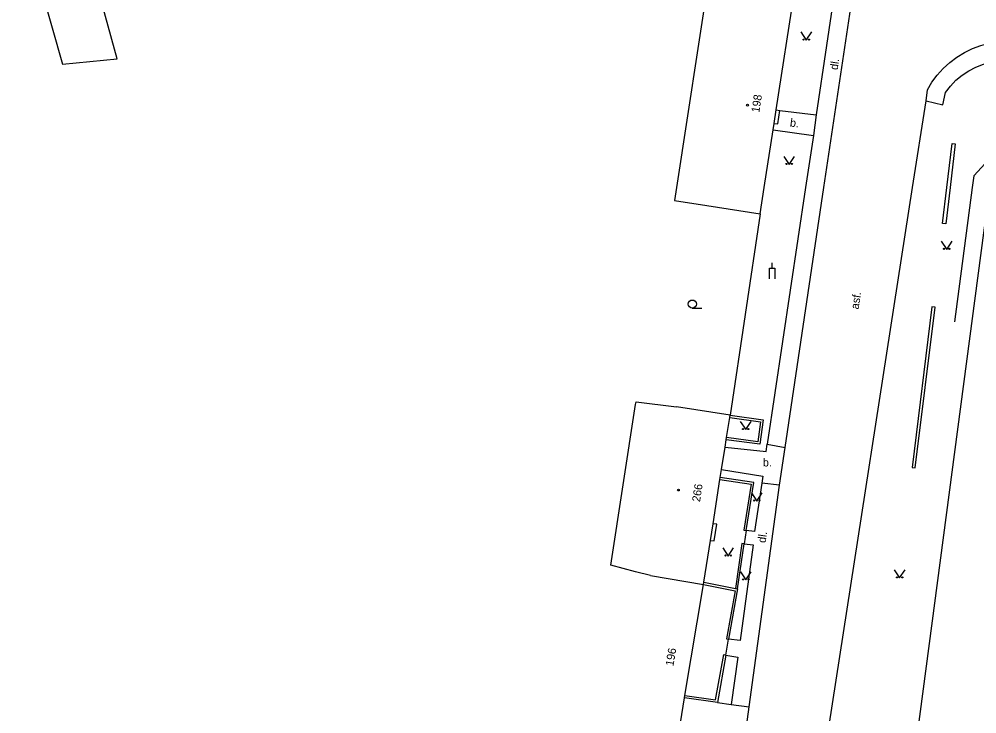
# Model space of a CAD drawing. Extents: x -582162 to -561283, y -1187583 to -1183539.
# Drawn here: x -575057.1 to -574968.4, y -1184048.7 to -1183984.4 of the extents above; entities that cross this region are included whole.
import ezdxf

# ---------------------------------------------------------------- set-up
doc = ezdxf.new("R2010")
doc.units = 0
for name, color, linetype in [('Vrstva 1', 7, 'Continuous'), ('Vrstva 10', 7, 'Continuous'), ('Vrstva 14', 7, 'Continuous'), ('Vrstva 3', 7, 'Continuous'), ('Vrstva 4', 7, 'Continuous'), ('Vrstva 5', 7, 'Continuous'), ('Vrstva 6', 7, 'Continuous'), ('Vrstva 8', 7, 'Continuous'), ('Vrstva 9', 7, 'Continuous')]:
    doc.layers.add(name, color=color, linetype=linetype)

# ---------------------------------------------------------------- blocks, each defined once
blk = doc.blocks.new('3.040')
at = {"layer": 'Vrstva 1'}
blk.add_line((0, -0.75), (1.75, -0.75), dxfattribs=at)
blk.add_circle((0, 0), 0.75, dxfattribs=at)
blk = doc.blocks.new('3.140')
at = {"layer": 'Vrstva 1'}
blk.add_lwpolyline([(-1, 1.5), (0, 0), (1, 1.5)], dxfattribs=at)
for centre in [(-0.5, 0.1), (0.5, 0.1)]:
    blk.add_circle(centre, 0.1, dxfattribs=at)
blk = doc.blocks.new('4.020')
at = {"layer": 'Vrstva 1'}
blk.add_circle((0, 0), 0.175, dxfattribs=at)
blk = doc.blocks.new('4.120')
at = {"layer": 'Vrstva 1'}
blk.add_line((0, 2), (0, 3), dxfattribs=at)
blk.add_lwpolyline([(-0.5, 0), (-0.5, 2), (0.5, 2), (0.5, 0)], dxfattribs=at)

msp = doc.modelspace()

# ---------------------------------------------------------------- linework, layer by layer
at = {"layer": 'Vrstva 10'}
for points in [[(-574982.59, -1184000), (-574979.64, -1183980.23), (-574979.73, -1183979.92), (-574979.89, -1183979.63), (-574980.11, -1183979.4), (-574980.38, -1183979.22), (-574980.69, -1183979.12), (-574980.84, -1183979.1), (-574991.91, -1183976.49)], [(-574992.2, -1183977.87), (-574981.38, -1183980.41), (-574983.3, -1183993.27)], [(-574973.13, -1183991.97), (-574973, -1183990.96), (-574972.58, -1183990.25), (-574972.09, -1183989.59), (-574971.54, -1183988.97), (-574970.93, -1183988.42), (-574970.27, -1183987.92), (-574969.57, -1183987.49), (-574968.83, -1183987.13), (-574968.05, -1183986.84), (-574967.84, -1183986.78), (-574966.96, -1183986.67), (-574966.07, -1183986.64), (-574965.18, -1183986.7), (-574964.81, -1183986.74), (-574962.92, -1183987.44), (-574940.13, -1183995.55), (-574927.84, -1184000)], [(-574973.13, -1183991.97), (-574971.56, -1183992.33), (-574971.34, -1183991.19), (-574970.88, -1183990.61), (-574970.36, -1183990.07), (-574969.79, -1183989.6), (-574969.17, -1183989.19), (-574968.51, -1183988.85), (-574967.81, -1183988.58), (-574967.23, -1183988.42), (-574966.15, -1183988.57), (-574964.51, -1183989.14), (-574964.37, -1183988.73), (-574940.58, -1183997.21), (-574932.83, -1184000)], [(-574974.37, -1184000), (-574973.13, -1183991.97)], [(-574986.66, -1183992.86), (-574983.3, -1183993.27)], [(-574983.3, -1183993.27), (-574983.55, -1183995.19)], [(-574987.28, -1183994.67), (-574983.55, -1183995.19)], [(-574983.55, -1183995.19), (-574984.27, -1184000)], [(-574984.19, -1184112.37), (-574985.15, -1184111.93), (-574985.81, -1184111.44), (-574986.43, -1184110.88), (-574986.99, -1184110.26), (-574987.49, -1184109.59), (-574987.93, -1184108.87), (-574988.29, -1184108.12), (-574988.59, -1184107.33), (-574988.8, -1184106.52), (-574988.94, -1184105.7), (-574989, -1184104.86), (-574982.11, -1184050.01), (-574974.37, -1184000)], [(-574984.27, -1184000), (-574987.82, -1184023.77)], [(-574986.18, -1184024.06), (-574982.59, -1184000)], [(-574965.69, -1184110.12), (-574979.74, -1184104.56), (-574975.79, -1184064.83), (-574967.23, -1184000)], [(-574991.73, -1184024.03), (-574987.92, -1184024.44), (-574987.82, -1184023.77)], [(-574987.82, -1184023.77), (-574986.18, -1184024.06)], [(-574986.68, -1184027.56), (-574986.18, -1184024.06)], [(-574992.05, -1184026.11), (-574988.24, -1184026.74), (-574988.33, -1184027.37)], [(-574988.33, -1184027.37), (-574988.99, -1184031.84), (-574989.78, -1184031.76)], [(-574989.5, -1184048.09), (-574986.68, -1184027.56)], [(-574986.68, -1184027.56), (-574988.33, -1184027.37)], [(-574989.96, -1184032.99), (-574989.12, -1184033.09), (-574990.33, -1184041.95), (-574991.4, -1184041.82)], [(-574991.65, -1184043.29), (-574990.54, -1184043.48), (-574991.16, -1184047.88)], [(-574992.44, -1184047.68), (-574991.16, -1184047.88)], [(-574991.16, -1184047.88), (-574989.5, -1184048.09)], [(-574990.01, -1184051.95), (-574989.5, -1184048.09)]]:
    msp.add_lwpolyline(points, dxfattribs=at)
at = {"layer": 'Vrstva 4'}
for points in [[(-574987, -1183992.82), (-574985.31, -1183981.86), (-574993.22, -1183980.45)], [(-574987.19, -1183994.06), (-574987, -1183992.82)], [(-574987.28, -1183994.67), (-574987.19, -1183994.06)], [(-574988.1, -1184000), (-574987.28, -1183994.67)], [(-574988.47, -1184002.43), (-574988.1, -1184000)], [(-574993.41, -1184001.67), (-574988.47, -1184002.43)], [(-574991.27, -1184021.08), (-574996.22, -1184020.31)], [(-574991.3, -1184021.28), (-574991.27, -1184021.08)], [(-574991.59, -1184023.15), (-574991.3, -1184021.28)], [(-574991.73, -1184024.03), (-574991.62, -1184023.35)], [(-574991.62, -1184023.35), (-574991.59, -1184023.15)], [(-574992.05, -1184026.11), (-574991.73, -1184024.03)], [(-574992.17, -1184026.85), (-574992.05, -1184026.11)], [(-574992.84, -1184031.13), (-574992.2, -1184027.04)], [(-574992.2, -1184027.04), (-574992.17, -1184026.85)], [(-574993.08, -1184032.67), (-574992.84, -1184031.13)], [(-574993.68, -1184036.55), (-574993.08, -1184032.67)], [(-574998.64, -1184035.92), (-574993.71, -1184036.75)], [(-574995.44, -1184047.04), (-574993.71, -1184036.75)], [(-574993.71, -1184036.75), (-574993.68, -1184036.55)], [(-574996.08, -1184050.92), (-574995.47, -1184047.24)], [(-574995.47, -1184047.24), (-574995.44, -1184047.04)]]:
    msp.add_lwpolyline(points, dxfattribs=at)
at = {"layer": 'Vrstva 5'}
for points in [[(-575056.03, -1183966.25), (-575057.05, -1183974.43), (-575053.04, -1183988.57), (-575047.98, -1183988.08), (-575051.7, -1183974.5), (-575045.78, -1183975.13), (-575044.95, -1183967.32)], [(-574993.22, -1183980.45), (-574996.22, -1184000)], [(-574996.22, -1184000), (-574996.41, -1184001.21), (-574993.41, -1184001.67)], [(-575000, -1184035.57), (-575002.29, -1184034.97), (-575000, -1184020.1)], [(-575000, -1184020.1), (-574999.96, -1184019.84), (-574996.22, -1184020.31)], [(-574998.64, -1184035.92), (-575000, -1184035.57)]]:
    msp.add_lwpolyline(points, dxfattribs=at)
at = {"layer": 'Vrstva 9'}
for points in [[(-574987.19, -1183994.06), (-574986.83, -1183994.11), (-574986.66, -1183992.86)], [(-574987, -1183992.82), (-574986.66, -1183992.86)], [(-574971.2, -1184000), (-574970.72, -1183995.92), (-574970.42, -1183995.96), (-574970.9, -1184000)], [(-574964.35, -1183996.4), (-574966.64, -1183996.68), (-574968.7, -1183998.91), (-574968.85, -1184000)], [(-574970.9, -1184000), (-574971.3, -1184003.37), (-574971.6, -1184003.34)], [(-574971.6, -1184003.34), (-574971.2, -1184000)], [(-574968.85, -1184000), (-574970.5, -1184012.43)], [(-574988.47, -1184002.43), (-574991.27, -1184021.08)], [(-574972.29, -1184011.09), (-574972.59, -1184011.05), (-574974.42, -1184025.92), (-574974.12, -1184025.96), (-574972.29, -1184011.09)], [(-574991.27, -1184021.08), (-574988.21, -1184021.51), (-574988.52, -1184023.76), (-574991.62, -1184023.35)], [(-574991.3, -1184021.28), (-574988.44, -1184021.68), (-574988.69, -1184023.54), (-574991.59, -1184023.15)], [(-574992.2, -1184027.04), (-574989.3, -1184027.48), (-574989.98, -1184031.73), (-574989.78, -1184031.76)], [(-574989.78, -1184031.76), (-574989.07, -1184027.31), (-574992.17, -1184026.85)], [(-574993.08, -1184032.67), (-574992.73, -1184032.72), (-574992.5, -1184031.18), (-574992.84, -1184031.13)], [(-574989.78, -1184031.76), (-574989.96, -1184032.99)], [(-574989.96, -1184032.99), (-574990.16, -1184032.96), (-574990.77, -1184037.13)], [(-574990.57, -1184037.17), (-574989.96, -1184032.99)], [(-574993.71, -1184036.75), (-574990.8, -1184037.33), (-574991.6, -1184041.79), (-574991.4, -1184041.82)], [(-574993.68, -1184036.55), (-574990.77, -1184037.13)], [(-574990.57, -1184037.17), (-574991.4, -1184041.82)], [(-574990.77, -1184037.13), (-574990.57, -1184037.17)], [(-574991.65, -1184043.29), (-574991.4, -1184041.82)], [(-574995.44, -1184047.04), (-574992.6, -1184047.45), (-574991.85, -1184043.25), (-574991.65, -1184043.29)], [(-574991.65, -1184043.29), (-574992.44, -1184047.68)], [(-574992.44, -1184047.68), (-574995.47, -1184047.24)]]:
    msp.add_lwpolyline(points, dxfattribs=at)

# ---------------------------------------------------------------- block references
at = {"layer": 'Vrstva 3', "xscale": 0.5, "yscale": 0.5}
for name, p in [('3.140', (-574984.21, -1183986.35)), ('3.140', (-574985.8, -1183997.87)), ('3.140', (-574971.22, -1184005.73)), ('3.040', (-574994.76, -1184010.79)), ('3.140', (-574989.82, -1184022.42)), ('3.140', (-574988.79, -1184029.03)), ('3.140', (-574991.44, -1184034.12)), ('3.140', (-574989.8, -1184036.33)), ('3.140', (-574975.57, -1184036.15))]:
    msp.add_blockref(name, p, dxfattribs=at)
at = {"layer": 'Vrstva 8', "xscale": 0.5, "yscale": 0.5}
for p in [(-574989.66, -1183992.37), (-574996.05, -1184028.01)]:
    msp.add_blockref('4.020', p, dxfattribs=at)
at = {"layer": 'Vrstva 9', "xscale": 0.5, "yscale": 0.5}
msp.add_blockref('4.120', (-574987.38, -1184008.46), dxfattribs=at)

# ---------------------------------------------------------------- texts
at = {"layer": 'Vrstva 14'}
for s, rotation, p in [('dl.', 81.513, (-574981.31, -1183989.15)), ('b.', 352.192, (-574985.76, -1183994.34)), ('asf.', 81.202, (-574979.37, -1184011.31)), ('dl.', 82.189, (-574987.98, -1184032.94))]:
    msp.add_text(s, height=0.75, rotation=rotation, dxfattribs=at).set_placement(p)
msp.add_text('b.', height=0.75, dxfattribs=at).set_placement((-574988.23, -1184025.83))
at = {"layer": 'Vrstva 6'}
for s, rotation, p in [('198', 81.256, (-574988.56, -1183993.1)), ('266', 81.161, (-574994.05, -1184029.15)), ('196', 80.487, (-574996.51, -1184044.35))]:
    msp.add_text(s, height=0.75, rotation=rotation, dxfattribs=at).set_placement(p)

doc.saveas('drawing.dxf')
